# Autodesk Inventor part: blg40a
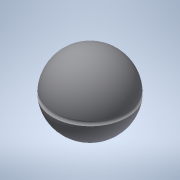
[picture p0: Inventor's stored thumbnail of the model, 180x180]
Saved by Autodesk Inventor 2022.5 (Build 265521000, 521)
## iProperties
Created: 2016-12
Part Number: blg40a
Material: 一般
Document SubType Name: Modeling
Designer: imaocorp
Density: 1 g/cm^3
Appearance: 既定
Author: imaocorp
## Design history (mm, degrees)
node "blg40a.x_t1"
node "blg40a"
node "Base1"
